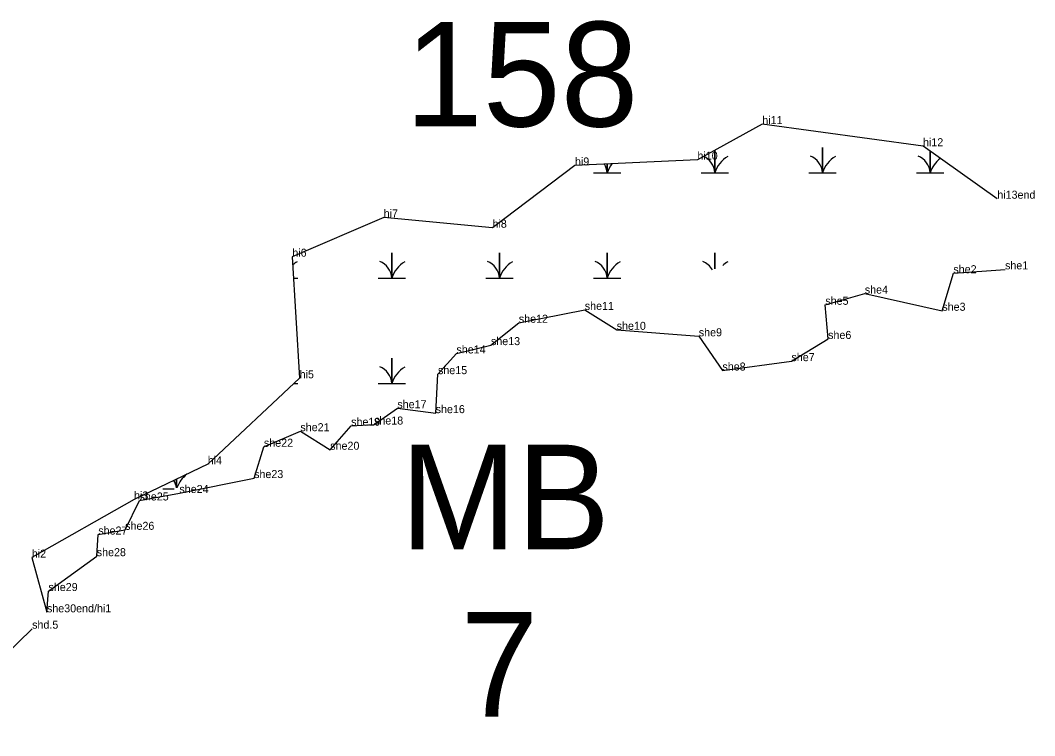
# Model space of a CAD drawing. Extents: x 2072529 to 2268796, y 436423 to 470397.
# Drawn here: x 2178325 to 2178958, y 450343 to 450790 of the extents above; entities that cross this region are included whole.
import ezdxf

# ---------------------------------------------------------------- set-up
doc = ezdxf.new("R2010")
doc.units = 0
for name, color, linetype in [('Default', 7, 'Continuous'), ('Exist Environmental Wetland Boundary', 7, 'Continuous'), ('Exist Environmental Wetland Boundary Cogo Comment', 7, 'Continuous'), ('Exist Environmental Wetland Boundary Cogo Point CELL', 7, 'Continuous'), ('Exist Hydro Jurisdictional Stream or Body of Water NEU Mitigable', 7, 'Continuous'), ('Exist Hydro Jurisdictional Stream or Body of Water NEU Mitigable Cogo Comment', 7, 'Continuous'), ('Exist Hydro Swamp or Marsh', 7, 'Continuous')]:
    doc.layers.add(name, color=color, linetype=linetype)

msp = doc.modelspace()

# ---------------------------------------------------------------- linework, layer by layer
at = {"layer": 'Exist Environmental Wetland Boundary'}
msp.add_lwpolyline([(2178934.99, 450678.47), (2178888.59, 450711.27), (2178788.18, 450725.04), (2178747.69, 450702.85), (2178671.19, 450699.25), (2178619.69, 450660.34), (2178551.72, 450666.82), (2178494.65, 450642.26), (2178499.23, 450566.31), (2178441.84, 450512.65), (2178395.81, 450490.65), (2178331.94, 450454.33), (2178341.39, 450420.15)], dxfattribs=at)
at = {"layer": 'Exist Environmental Wetland Boundary Cogo Point CELL'}
for p, q in [((2178788.18, 450725.04), (2178788.18, 450725.04)), ((2178888.59, 450711.27), (2178888.59, 450711.27)), ((2178747.69, 450702.85), (2178747.69, 450702.85)), ((2178671.19, 450699.25), (2178671.19, 450699.25)), ((2178934.99, 450678.47), (2178934.99, 450678.47)), ((2178551.72, 450666.82), (2178551.72, 450666.82)), ((2178619.69, 450660.34), (2178619.69, 450660.34)), ((2178494.65, 450642.26), (2178494.65, 450642.26)), ((2178939.82, 450634.35), (2178939.82, 450634.35)), ((2178907.54, 450631.95), (2178907.54, 450631.95)), ((2178852.23, 450619.2), (2178852.23, 450619.2)), ((2178677.33, 450609.04), (2178677.33, 450609.04)), ((2178827.57, 450612.23), (2178827.57, 450612.23)), ((2178900.65, 450608.5), (2178900.65, 450608.5)), ((2178636.13, 450601.01), (2178636.13, 450601.01)), ((2178697.25, 450596.59), (2178697.25, 450596.59)), ((2178748.54, 450592.55), (2178748.54, 450592.55)), ((2178829.32, 450590.9), (2178829.32, 450590.9)), ((2178618.72, 450587.04), (2178618.72, 450587.04)), ((2178597.15, 450581.84), (2178597.15, 450581.84)), ((2178806.41, 450577.03), (2178806.41, 450577.03)), ((2178763.29, 450571.17), (2178763.29, 450571.17)), ((2178499.23, 450566.31), (2178499.23, 450566.31)), ((2178585.63, 450568.9), (2178585.63, 450568.9)), ((2178560.25, 450547.61), (2178560.25, 450547.61)), ((2178584.19, 450544.55), (2178584.19, 450544.55)), ((2178499.69, 450533.28), (2178499.69, 450533.28)), ((2178531.41, 450536.68), (2178531.41, 450536.68)), ((2178545.67, 450537.44), (2178545.67, 450537.44)), ((2178476.92, 450523.55), (2178476.92, 450523.55)), ((2178518.32, 450521.7), (2178518.32, 450521.7)), ((2178441.84, 450512.65), (2178441.84, 450512.65)), ((2178470.78, 450504), (2178470.78, 450504)), ((2178424.11, 450494.66), (2178424.11, 450494.66)), ((2178395.81, 450490.65), (2178395.81, 450490.65)), ((2178399.2, 450490.02), (2178399.2, 450490.02)), ((2178373.45, 450468.74), (2178373.45, 450468.74)), ((2178390.24, 450471.68), (2178390.24, 450471.68)), ((2178331.94, 450454.33), (2178331.94, 450454.33)), ((2178372.49, 450455.22), (2178372.49, 450455.22)), ((2178342.34, 450433.44), (2178342.34, 450433.44)), ((2178341.39, 450420.15), (2178341.39, 450420.15)), ((2178341.39, 450420.15), (2178341.39, 450420.15)), ((2178332.13, 450409.94), (2178332.13, 450409.94))]:
    msp.add_line(p, q, dxfattribs=at)
at = {"layer": 'Exist Hydro Jurisdictional Stream or Body of Water NEU Mitigable'}
for points in [[(2178341.39, 450420.15), (2178342.34, 450433.44), (2178372.49, 450455.22), (2178373.45, 450468.74), (2178390.24, 450471.68), (2178399.2, 450490.02), (2178424.11, 450494.66), (2178470.78, 450504), (2178476.92, 450523.55), (2178499.69, 450533.28), (2178518.32, 450521.7), (2178531.41, 450536.68), (2178545.67, 450537.44), (2178560.25, 450547.61), (2178584.19, 450544.55), (2178585.63, 450568.9), (2178597.15, 450581.84), (2178618.72, 450587.04), (2178636.13, 450601.01), (2178677.33, 450609.04), (2178697.25, 450596.59), (2178748.54, 450592.55), (2178763.29, 450571.17), (2178806.41, 450577.03), (2178829.32, 450590.9), (2178827.57, 450612.23), (2178852.23, 450619.2), (2178900.65, 450608.5), (2178907.54, 450631.95), (2178939.82, 450634.35)], [(2178221.35, 450343.23), (2178253.43, 450343.09), (2178279.19, 450358.33), (2178332.13, 450409.94)]]:
    msp.add_lwpolyline(points, dxfattribs=at)
at = {"layer": 'Exist Hydro Swamp or Marsh'}
for points in [[(2178817.22, 450694.68), (2178825.82, 450694.68), (2178825.82, 450710.46), (2178825.82, 450694.68), (2178834.42, 450694.68)], [(2178749.97, 450694.68), (2178758.57, 450694.68), (2178758.57, 450708.81)], [(2178758.57, 450708.81), (2178758.57, 450694.68), (2178767.17, 450694.68)], [(2178884.47, 450694.68), (2178893.07, 450694.68), (2178893.07, 450708.1)], [(2178893.07, 450708.1), (2178893.07, 450694.68), (2178901.67, 450694.68)], [(2178682.72, 450694.68), (2178691.32, 450694.68), (2178691.32, 450700.2)], [(2178691.32, 450700.2), (2178691.32, 450694.68), (2178699.92, 450694.68)], [(2178548.22, 450628.88), (2178556.82, 450628.88), (2178556.82, 450644.66), (2178556.82, 450628.88), (2178565.42, 450628.88)], [(2178615.47, 450628.88), (2178624.07, 450628.88), (2178624.07, 450644.66), (2178624.07, 450628.88), (2178632.67, 450628.88)], [(2178682.72, 450628.88), (2178691.32, 450628.88), (2178691.32, 450644.66), (2178691.32, 450628.88), (2178699.92, 450628.88)], [(2178758.57, 450634.7), (2178758.57, 450644.66), (2178758.57, 450634.7)], [(2178495.46, 450628.88), (2178498.17, 450628.88)], [(2178548.22, 450563.08), (2178556.82, 450563.08), (2178556.82, 450578.86), (2178556.82, 450563.08), (2178565.42, 450563.08)], [(2178495.77, 450563.08), (2178498.17, 450563.08)], [(2178422.32, 450497.9), (2178422.32, 450503.32)], [(2178422.32, 450503.32), (2178422.32, 450497.9)], [(2178413.72, 450497.28), (2178420.79, 450497.28)]]:
    msp.add_lwpolyline(points, dxfattribs=at)
for centre, radius, start, end in [((2178746.3, 450693.79), 12.3, 4.14034, 65.00382), ((2178776.81, 450688.62), 19.22, 122.12745, 161.62219), ((2178813.55, 450693.79), 12.3, 4.14034, 67.53497), ((2178844.06, 450688.62), 19.22, 122.12745, 161.62219), ((2178880.8, 450693.79), 12.3, 4.14034, 67.53497), ((2178911.31, 450688.62), 19.22, 128.48944, 161.62219), ((2178679.05, 450693.79), 12.3, 4.14034, 30.94468), ((2178709.56, 450688.62), 19.22, 142.4369, 161.62219), ((2178544.55, 450627.99), 12.3, 4.14034, 67.53497), ((2178611.8, 450627.99), 12.3, 4.14034, 67.53497), ((2178679.05, 450627.99), 12.3, 4.14034, 67.53497), ((2178746.3, 450627.99), 12.3, 29.58395, 67.53497), ((2178507.81, 450622.82), 19.22, 122.12745, 131.9623), ((2178575.06, 450622.82), 19.22, 122.12745, 161.62219), ((2178642.31, 450622.82), 19.22, 122.12745, 161.62219), ((2178709.56, 450622.82), 19.22, 122.12745, 161.62219), ((2178776.81, 450622.82), 19.22, 122.12745, 133.66355), ((2178544.55, 450562.19), 12.3, 4.14034, 67.53497), ((2178575.06, 450557.02), 19.22, 122.12745, 161.62219), ((2178440.56, 450491.22), 19.22, 127.74839, 159.32809), ((2178410.05, 450496.39), 12.3, 6.93569, 30.0422)]:
    msp.add_arc(centre, radius, start, end, dxfattribs=at)

# ---------------------------------------------------------------- texts
at = {"layer": 'Default'}
for s, p in [('158', (2178565.05, 450723.6)), ('MB', (2178562, 450459.56)), ('7', (2178599.7, 450355.02))]:
    msp.add_text(s, height=65.34, dxfattribs=at).set_placement(p)
at = {"layer": 'Exist Environmental Wetland Boundary Cogo Comment'}
for s, p in [('hi11', (2178788.18, 450725.04)), ('hi12', (2178888.59, 450711.27)), ('hi9', (2178671.19, 450699.25)), ('hi10', (2178747.69, 450702.85)), ('hi13end', (2178934.99, 450678.47)), ('hi7', (2178551.72, 450666.82)), ('hi8', (2178619.69, 450660.34)), ('hi6', (2178494.65, 450642.26)), ('hi5', (2178499.23, 450566.31)), ('hi4', (2178441.84, 450512.65)), ('hi2', (2178331.94, 450454.33))]:
    msp.add_text(s, height=5, dxfattribs=at).set_placement(p)
at = {"layer": 'Exist Hydro Jurisdictional Stream or Body of Water NEU Mitigable Cogo Comment'}
for s, p in [('she1', (2178939.82, 450634.35)), ('she2', (2178907.54, 450631.95)), ('she4', (2178852.23, 450619.2)), ('she11', (2178677.33, 450609.04)), ('she5', (2178827.57, 450612.23)), ('she3', (2178900.65, 450608.5)), ('she12', (2178636.13, 450601.01)), ('she10', (2178697.25, 450596.59)), ('she9', (2178748.54, 450592.55)), ('she6', (2178829.32, 450590.9)), ('she13', (2178618.72, 450587.04)), ('she14', (2178597.15, 450581.84)), ('she7', (2178806.41, 450577.03)), ('she8', (2178763.29, 450571.17)), ('she15', (2178585.63, 450568.9)), ('she17', (2178560.25, 450547.61)), ('she16', (2178584.19, 450544.55)), ('she21', (2178499.69, 450533.28)), ('she19', (2178531.41, 450536.68)), ('she18', (2178545.67, 450537.44)), ('she22', (2178476.92, 450523.55)), ('she20', (2178518.32, 450521.7)), ('she23', (2178470.78, 450504)), ('she24', (2178424.11, 450494.66)), ('hi3', (2178395.81, 450490.65)), ('she25', (2178399.2, 450490.02)), ('she26', (2178390.24, 450471.68)), ('she27', (2178373.45, 450468.74)), ('she28', (2178372.49, 450455.22)), ('she29', (2178342.34, 450433.44)), ('she30end/hi1', (2178341.39, 450420.15)), ('shd.5', (2178332.13, 450409.94))]:
    msp.add_text(s, height=5, dxfattribs=at).set_placement(p)

doc.saveas('drawing.dxf')
